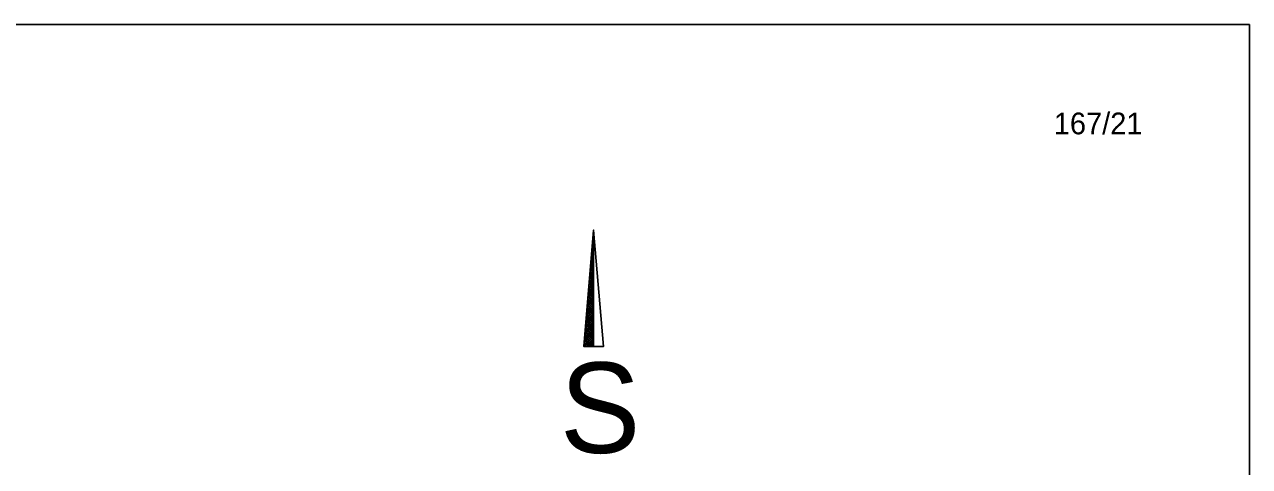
# Model space of a CAD drawing. Extents: x -400488 to -400124, y -1251493 to -1251223.
# Drawn here: x -400275.66 to -400250.43, y -1251242.18 to -1251233.09 of the extents above; entities that cross this region are included whole.
import ezdxf

# ---------------------------------------------------------------- set-up
doc = ezdxf.new("R2010")
doc.units = 0
doc.layers.add('Level 3', color=7, linetype='Continuous')

msp = doc.modelspace()

# ---------------------------------------------------------------- linework, layer by layer
at = {"layer": 'Level 3'}
for p, q in [((-400263.956, -1251237.56), (-400263.936, -1251237.539)), ((-400263.952, -1251237.516), (-400263.936, -1251237.5)), ((-400263.952, -1251237.516), (-400263.936, -1251237.533)), ((-400263.949, -1251237.473), (-400263.936, -1251237.46)), ((-400263.949, -1251237.479), (-400263.936, -1251237.493)), ((-400263.946, -1251237.443), (-400263.936, -1251237.454)), ((-400263.945, -1251237.43), (-400263.936, -1251237.42)), ((-400263.943, -1251237.406), (-400263.936, -1251237.414)), ((-400263.942, -1251237.387), (-400263.936, -1251237.381)), ((-400263.94, -1251237.37), (-400263.936, -1251237.374)), ((-400263.938, -1251237.344), (-400263.936, -1251237.341)), ((-400263.937, -1251237.333), (-400263.936, -1251237.335)), ((-400263.978, -1251237.819), (-400263.936, -1251237.777)), ((-400263.974, -1251237.776), (-400263.936, -1251237.737)), ((-400263.974, -1251237.772), (-400263.936, -1251237.81)), ((-400263.971, -1251237.735), (-400263.936, -1251237.77)), ((-400263.97, -1251237.732), (-400263.936, -1251237.698)), ((-400263.968, -1251237.699), (-400263.936, -1251237.731)), ((-400263.967, -1251237.689), (-400263.936, -1251237.658)), ((-400263.965, -1251237.662), (-400263.936, -1251237.691)), ((-400263.963, -1251237.646), (-400263.936, -1251237.618)), ((-400263.962, -1251237.626), (-400263.936, -1251237.651)), ((-400263.96, -1251237.603), (-400263.936, -1251237.579)), ((-400263.959, -1251237.589), (-400263.936, -1251237.612)), ((-400263.955, -1251237.553), (-400263.936, -1251237.572)), ((-400263.999, -1251238.078), (-400263.936, -1251238.014)), ((-400263.996, -1251238.035), (-400263.936, -1251237.975)), ((-400263.995, -1251238.028), (-400263.936, -1251238.087)), ((-400263.992, -1251237.992), (-400263.936, -1251237.935)), ((-400263.992, -1251237.991), (-400263.936, -1251238.047)), ((-400263.989, -1251237.955), (-400263.936, -1251238.008)), ((-400263.988, -1251237.948), (-400263.936, -1251237.896)), ((-400263.986, -1251237.918), (-400263.936, -1251237.968)), ((-400263.985, -1251237.905), (-400263.936, -1251237.856)), ((-400263.983, -1251237.882), (-400263.936, -1251237.929)), ((-400263.981, -1251237.862), (-400263.936, -1251237.816)), ((-400263.98, -1251237.845), (-400263.936, -1251237.889)), ((-400263.977, -1251237.808), (-400263.936, -1251237.849)), ((-400264.024, -1251238.38), (-400263.936, -1251238.292)), ((-400264.021, -1251238.337), (-400263.936, -1251238.252)), ((-400264.017, -1251238.294), (-400263.936, -1251238.212)), ((-400264.016, -1251238.284), (-400263.936, -1251238.364)), ((-400264.014, -1251238.251), (-400263.936, -1251238.173)), ((-400264.013, -1251238.247), (-400263.936, -1251238.325)), ((-400264.01, -1251238.208), (-400263.936, -1251238.133)), ((-400264.01, -1251238.21), (-400263.936, -1251238.285)), ((-400264.007, -1251238.174), (-400263.936, -1251238.245)), ((-400264.006, -1251238.164), (-400263.936, -1251238.094)), ((-400264.004, -1251238.137), (-400263.936, -1251238.206)), ((-400264.003, -1251238.121), (-400263.936, -1251238.054)), ((-400264.001, -1251238.101), (-400263.936, -1251238.166)), ((-400263.998, -1251238.064), (-400263.936, -1251238.127)), ((-400264.046, -1251238.64), (-400263.936, -1251238.529)), ((-400264.042, -1251238.596), (-400263.936, -1251238.49)), ((-400264.039, -1251238.553), (-400263.936, -1251238.45)), ((-400264.038, -1251238.539), (-400263.936, -1251238.641)), ((-400264.035, -1251238.51), (-400263.936, -1251238.41)), ((-400264.035, -1251238.503), (-400263.936, -1251238.602)), ((-400264.032, -1251238.467), (-400263.936, -1251238.371)), ((-400264.032, -1251238.466), (-400263.936, -1251238.562)), ((-400264.029, -1251238.43), (-400263.936, -1251238.523)), ((-400264.028, -1251238.424), (-400263.936, -1251238.331)), ((-400264.026, -1251238.393), (-400263.936, -1251238.483)), ((-400264.023, -1251238.357), (-400263.936, -1251238.443)), ((-400264.019, -1251238.32), (-400263.936, -1251238.404)), ((-400264.068, -1251238.899), (-400263.936, -1251238.767)), ((-400264.064, -1251238.856), (-400263.936, -1251238.727)), ((-400264.061, -1251238.812), (-400263.936, -1251238.688)), ((-400264.059, -1251238.795), (-400263.936, -1251238.919)), ((-400264.057, -1251238.769), (-400263.936, -1251238.648)), ((-400264.056, -1251238.759), (-400263.936, -1251238.879)), ((-400264.053, -1251238.726), (-400263.936, -1251238.608)), ((-400264.053, -1251238.722), (-400263.936, -1251238.839)), ((-400264.05, -1251238.683), (-400263.936, -1251238.569)), ((-400264.05, -1251238.686), (-400263.936, -1251238.8)), ((-400264.047, -1251238.649), (-400263.936, -1251238.76)), ((-400264.044, -1251238.613), (-400263.936, -1251238.721)), ((-400264.041, -1251238.576), (-400263.936, -1251238.681)), ((-400264.093, -1251239.201), (-400263.936, -1251239.044)), ((-400264.089, -1251239.158), (-400263.936, -1251239.004)), ((-400264.086, -1251239.115), (-400263.936, -1251238.965)), ((-400264.082, -1251239.072), (-400263.936, -1251238.925)), ((-400264.08, -1251239.051), (-400263.936, -1251239.196)), ((-400264.079, -1251239.028), (-400263.936, -1251238.886)), ((-400264.077, -1251239.015), (-400263.936, -1251239.156)), ((-400264.075, -1251238.985), (-400263.936, -1251238.846)), ((-400264.074, -1251238.978), (-400263.936, -1251239.117)), ((-400264.071, -1251238.942), (-400263.936, -1251238.806)), ((-400264.071, -1251238.941), (-400263.936, -1251239.077)), ((-400264.068, -1251238.905), (-400263.936, -1251239.037)), ((-400264.065, -1251238.868), (-400263.936, -1251238.998)), ((-400264.062, -1251238.832), (-400263.936, -1251238.958)), ((-400264.115, -1251239.46), (-400263.936, -1251239.282)), ((-400264.111, -1251239.417), (-400263.936, -1251239.242)), ((-400264.107, -1251239.374), (-400263.936, -1251239.202)), ((-400264.104, -1251239.331), (-400263.936, -1251239.163)), ((-400264.1, -1251239.288), (-400263.936, -1251239.123)), ((-400264.099, -1251239.27), (-400263.936, -1251239.433)), ((-400264.097, -1251239.244), (-400263.936, -1251239.084)), ((-400264.096, -1251239.234), (-400263.936, -1251239.394)), ((-400264.093, -1251239.197), (-400263.936, -1251239.354)), ((-400264.09, -1251239.161), (-400263.936, -1251239.315)), ((-400264.087, -1251239.124), (-400263.936, -1251239.275)), ((-400264.083, -1251239.088), (-400263.936, -1251239.235)), ((-400264.133, -1251239.676), (-400263.936, -1251239.48)), ((-400264.13, -1251239.714), (-400263.936, -1251239.519)), ((-400264.129, -1251239.633), (-400263.936, -1251239.44)), ((-400264.125, -1251239.59), (-400263.936, -1251239.4)), ((-400264.122, -1251239.547), (-400263.936, -1251239.361)), ((-400264.12, -1251239.526), (-400263.936, -1251239.711)), ((-400264.118, -1251239.504), (-400263.936, -1251239.321)), ((-400264.117, -1251239.49), (-400263.936, -1251239.671)), ((-400264.114, -1251239.453), (-400263.936, -1251239.631)), ((-400264.111, -1251239.417), (-400263.936, -1251239.592)), ((-400264.108, -1251239.38), (-400263.936, -1251239.552)), ((-400264.105, -1251239.344), (-400263.936, -1251239.513)), ((-400264.102, -1251239.307), (-400263.936, -1251239.473)), ((-400264.135, -1251239.709), (-400264.131, -1251239.714)), ((-400264.132, -1251239.673), (-400264.091, -1251239.714)), ((-400264.129, -1251239.636), (-400264.052, -1251239.714)), ((-400264.126, -1251239.599), (-400264.012, -1251239.714)), ((-400264.123, -1251239.563), (-400263.972, -1251239.714)), ((-400264.09, -1251239.714), (-400263.936, -1251239.559)), ((-400264.051, -1251239.714), (-400263.936, -1251239.598)), ((-400264.011, -1251239.714), (-400263.936, -1251239.638)), ((-400263.972, -1251239.714), (-400263.936, -1251239.678))]:
    msp.add_line(p, q, dxfattribs=at)
msp.add_lwpolyline([(-400397.431, -1251233.087), (-400250.431, -1251233.087), (-400250.431, -1251440.987), (-400397.431, -1251440.987)], close=True, dxfattribs=at)
msp.add_lwpolyline([(-400263.936, -1251237.316), (-400264.136, -1251239.714), (-400263.736, -1251239.714), (-400263.936, -1251237.316), (-400263.936, -1251239.712)], dxfattribs=at)

# ---------------------------------------------------------------- texts
for s, height, p in [('167/21', 0.4466, (-400254.461, -1251235.346)), ('S', 1.86, (-400264.632, -1251241.902))]:
    msp.add_text(s, height=height, rotation=0.0072, dxfattribs=at).set_placement(p)

doc.saveas('drawing.dxf')
